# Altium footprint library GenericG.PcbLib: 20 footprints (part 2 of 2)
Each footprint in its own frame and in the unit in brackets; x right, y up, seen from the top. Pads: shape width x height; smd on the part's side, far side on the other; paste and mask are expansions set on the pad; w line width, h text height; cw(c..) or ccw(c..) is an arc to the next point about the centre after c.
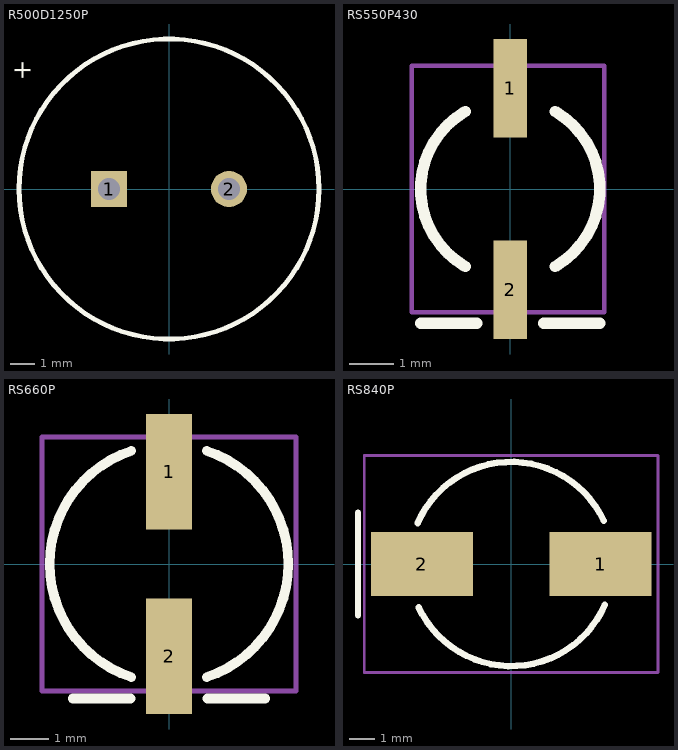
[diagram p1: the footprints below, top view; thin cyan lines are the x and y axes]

## R500D1250P [mm] "Radial, 5mm lead spacing and 12.5mm diameter, polarized"
height 20
pads (2):
  rect 1.5x1.5 hole 0.9: 1(-2.5,0)
  round 1.5 hole 0.9: 2(2.5,0)
Top Overlay:
  circle w0.2: c0,0 r6.25
  text "+" at -5.75,4.5 h0.76
3D body: height 20, standoff 0, extent -6.25,-6.25 6.25,6.25

## RS550P430 [mm] "Surface-mount cap, 5.5x4.3mm, polarized"
height 5.8
pads (2):
  rect 0.75x2.2 smd: 1(0,2.25) 2(0,-2.25)
Top Overlay:
  lines w0.254: -2,-3 -0.75,-3 ; -1,-1.732 cw(c0,0) -1,1.732 ; 0.75,-3 2,-3 ; 1,-1.732 ccw(c0,0) 1,1.732
Mechanical 15:
  lines w0.1: -2.2,-2.75 -2.2,2.75 2.1,2.75 2.1,-2.75 -2.2,-2.75
3D body: height 5.8, standoff 0, extent -1.984,-1.996 2,1.996
3D body: height 1, standoff 0, extent -2.2,-2.75 2.1,2.75

## RS660P [mm] "Surface-mount cap, 6.6x6.6mm, polarized"
height 7.7
pads (2):
  rect 1.2x3 smd: 1(0,2.4) 2(0,-2.4)
Top Overlay:
  lines w0.254: -2.5,-3.5 -1,-3.5 ; -0.981,-2.942 cw(c0,0) -0.981,2.942 ; 0.981,-2.942 ccw(c0,0) 0.981,2.942 ; 1,-3.5 2.5,-3.5
Mechanical 15:
  lines w0.127: -3.3,-3.3 3.3,-3.3 3.3,3.3 -3.3,3.3 -3.3,-3.3
3D body: height 7.7, standoff 0, extent -3.125,-3.144 3.15,3.144

## RS840P [mm] "Surface-mount cap, 8.4mm x 8.4mm, polarized"
height 10
pads (2):
  rect 4x2.5 smd: 1(3.5,0) 2(-3.5,0)
Top Overlay:
  lines w0.254: -6,-2 -6,2 ; -3.665,1.603 cw(c0,0) 3.625,1.692 ; -3.625,-1.692 ccw(c0,0) 3.665,-1.603
Mechanical 15:
  lines w0.1: -5.75,-4.25 5.75,-4.25 5.75,4.25 -5.75,4.25 -5.75,-4.25
3D body: height 10, standoff 0, extent -3.968,-3.992 4,3.992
